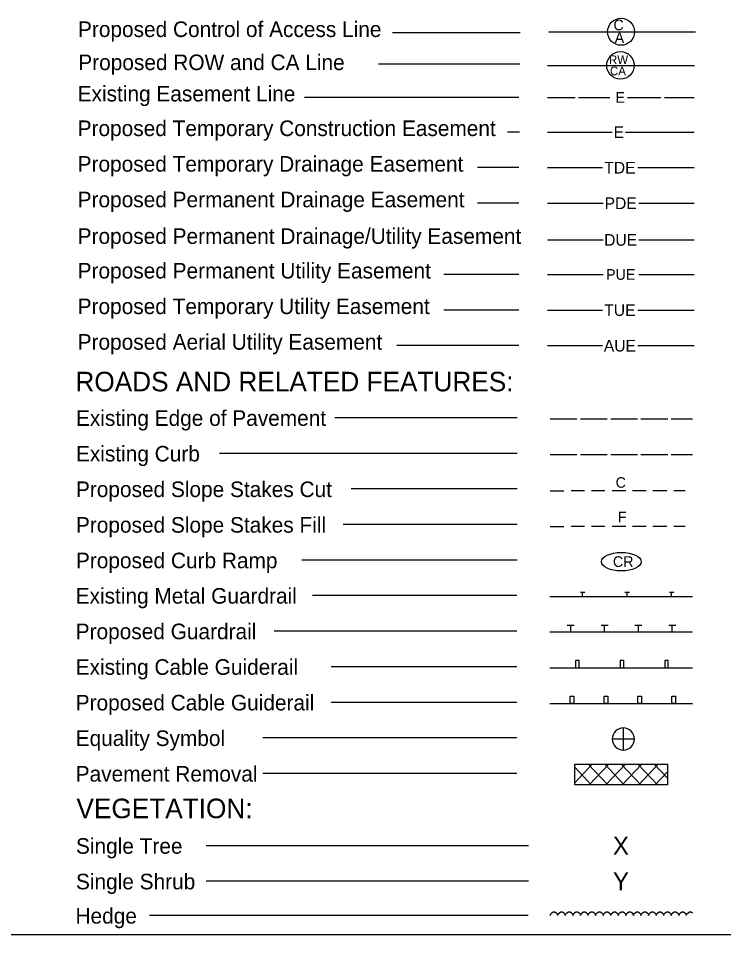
# Model space of a CAD drawing. Extents: x 2025847 to 2026166, y 840763 to 840870.
# Drawn here: x 2025880.57 to 2025913.87, y 840762.86 to 840806.14 of the extents above; entities that cross this region are included whole.
import ezdxf

# ---------------------------------------------------------------- set-up
doc = ezdxf.new("R2010")
doc.units = 0
for name, color, linetype in [('P_RDY_Easement_Permanent_Drainage_Utility', 7, 'Continuous'), ('P_RDY_WCC_CELL', 7, 'Continuous'), ('Sheet_Plan_CELL', 7, 'Continuous'), ('Sheet_Symbology_CELL', 7, 'Continuous')]:
    doc.layers.add(name, color=color, linetype=linetype)

msp = doc.modelspace()

# ---------------------------------------------------------------- linework, layer by layer
at = {"layer": 'P_RDY_Easement_Permanent_Drainage_Utility'}
for p, q in [((2025905.546, 840795.677), (2025908.178, 840795.677)), ((2025909.86, 840795.677), (2025912.483, 840795.677))]:
    msp.add_line(p, q, dxfattribs=at)
at = {"layer": 'P_RDY_WCC_CELL'}
msp.add_ellipse((2025909.036, 840780.474), major_axis=(0.943, 0), ratio=0.462467, dxfattribs=at)
at = {"layer": 'Sheet_Plan_CELL'}
msp.add_line((2025847.266, 840762.856), (2025982.68, 840762.856), dxfattribs=at)
at = {"layer": 'Sheet_Symbology_CELL'}
for p, q in [((2025904.26, 840805.465), (2025898.236, 840805.465)), ((2025905.608, 840805.497), (2025912.545, 840805.497)), ((2025904.252, 840803.972), (2025897.579, 840803.972)), ((2025905.547, 840803.907), (2025912.484, 840803.907)), ((2025904.199, 840802.406), (2025894.085, 840802.406)), ((2025905.546, 840802.406), (2025906.851, 840802.406)), ((2025907.019, 840802.406), (2025908.49, 840802.406)), ((2025909.331, 840802.406), (2025910.907, 840802.406)), ((2025911.076, 840802.406), (2025912.483, 840802.406)), ((2025904.231, 840800.771), (2025903.67, 840800.771)), ((2025905.546, 840800.771), (2025905.766, 840800.771)), ((2025905.766, 840800.771), (2025908.604, 840800.771)), ((2025909.234, 840800.771), (2025912.072, 840800.771)), ((2025912.072, 840800.771), (2025912.483, 840800.771)), ((2025904.199, 840799.089), (2025902.252, 840799.089)), ((2025905.546, 840799.089), (2025905.828, 840799.089)), ((2025905.828, 840799.089), (2025908.14, 840799.089)), ((2025909.822, 840799.089), (2025912.134, 840799.089)), ((2025912.134, 840799.089), (2025912.483, 840799.089)), ((2025904.199, 840797.408), (2025902.252, 840797.408)), ((2025905.546, 840797.408), (2025905.866, 840797.408)), ((2025905.866, 840797.408), (2025908.178, 840797.408)), ((2025909.86, 840797.408), (2025912.172, 840797.408)), ((2025912.172, 840797.408), (2025912.483, 840797.408)), ((2025904.199, 840794.044), (2025900.656, 840794.044)), ((2025905.546, 840794.044), (2025905.869, 840794.044)), ((2025905.869, 840794.044), (2025908.181, 840794.044)), ((2025909.863, 840794.044), (2025912.175, 840794.044)), ((2025912.175, 840794.044), (2025912.483, 840794.044)), ((2025904.199, 840792.362), (2025900.656, 840792.362)), ((2025905.546, 840792.362), (2025905.828, 840792.362)), ((2025905.828, 840792.362), (2025908.14, 840792.362)), ((2025909.822, 840792.362), (2025912.134, 840792.362)), ((2025912.134, 840792.362), (2025912.483, 840792.362)), ((2025904.199, 840790.681), (2025898.443, 840790.681)), ((2025905.546, 840790.681), (2025905.828, 840790.681)), ((2025905.828, 840790.681), (2025908.14, 840790.681)), ((2025909.822, 840790.681), (2025912.134, 840790.681)), ((2025912.134, 840790.681), (2025912.483, 840790.681)), ((2025904.118, 840787.273), (2025895.512, 840787.273)), ((2025905.676, 840787.225), (2025906.937, 840787.225)), ((2025907.105, 840787.225), (2025908.366, 840787.225)), ((2025908.534, 840787.225), (2025909.796, 840787.225)), ((2025909.964, 840787.225), (2025911.225, 840787.225)), ((2025911.393, 840787.225), (2025912.402, 840787.225)), ((2025904.118, 840785.592), (2025890.064, 840785.592)), ((2025905.676, 840785.543), (2025906.937, 840785.543)), ((2025907.105, 840785.543), (2025908.366, 840785.543)), ((2025908.534, 840785.543), (2025909.796, 840785.543)), ((2025909.964, 840785.543), (2025911.225, 840785.543)), ((2025911.393, 840785.543), (2025912.402, 840785.543)), ((2025904.118, 840783.91), (2025896.283, 840783.91)), ((2025905.676, 840783.822), (2025906.315, 840783.822)), ((2025907.298, 840783.822), (2025906.664, 840783.822)), ((2025908.265, 840783.822), (2025907.626, 840783.822)), ((2025909.253, 840783.822), (2025908.597, 840783.822)), ((2025910.216, 840783.822), (2025909.564, 840783.822)), ((2025911.187, 840783.822), (2025910.527, 840783.822)), ((2025912.053, 840783.822), (2025911.515, 840783.822)), ((2025904.118, 840782.229), (2025895.9, 840782.229)), ((2025905.676, 840782.14), (2025906.315, 840782.14)), ((2025907.298, 840782.14), (2025906.664, 840782.14)), ((2025908.265, 840782.14), (2025907.626, 840782.14)), ((2025909.253, 840782.14), (2025908.597, 840782.14)), ((2025910.216, 840782.14), (2025909.564, 840782.14)), ((2025911.187, 840782.14), (2025910.527, 840782.14)), ((2025912.053, 840782.14), (2025911.515, 840782.14)), ((2025904.118, 840780.547), (2025893.95, 840780.547)), ((2025904.105, 840778.876), (2025894.449, 840778.876)), ((2025905.663, 840778.827), (2025912.389, 840778.827)), ((2025907.103, 840779.037), (2025907.314, 840779.037)), ((2025907.209, 840778.827), (2025907.209, 840779.037)), ((2025909.205, 840779.037), (2025909.416, 840779.037)), ((2025909.31, 840778.827), (2025909.31, 840779.037)), ((2025911.307, 840779.037), (2025911.518, 840779.037)), ((2025911.412, 840778.827), (2025911.412, 840779.037)), ((2025904.105, 840777.194), (2025892.65, 840777.194)), ((2025912.389, 840777.146), (2025905.663, 840777.146)), ((2025906.48, 840777.478), (2025906.817, 840777.478)), ((2025906.648, 840777.146), (2025906.648, 840777.478)), ((2025908.078, 840777.478), (2025908.414, 840777.478)), ((2025908.246, 840777.146), (2025908.246, 840777.478)), ((2025909.675, 840777.478), (2025910.011, 840777.478)), ((2025909.843, 840777.146), (2025909.843, 840777.478)), ((2025911.273, 840777.478), (2025911.609, 840777.478)), ((2025911.441, 840777.146), (2025911.441, 840777.478)), ((2025904.105, 840775.512), (2025895.335, 840775.512)), ((2025905.663, 840775.464), (2025912.389, 840775.464)), ((2025904.105, 840773.831), (2025895.335, 840773.831)), ((2025905.663, 840773.783), (2025912.389, 840773.783)), ((2025909.129, 840772.625), (2025909.129, 840772.1)), ((2025904.105, 840772.149), (2025892.113, 840772.149)), ((2025908.603, 840772.1), (2025909.129, 840772.1)), ((2025909.129, 840772.1), (2025909.129, 840771.574)), ((2025909.129, 840772.1), (2025909.654, 840772.1)), ((2025906.835, 840770.912), (2025911.216, 840770.912)), ((2025906.835, 840769.929), (2025906.835, 840770.912)), ((2025906.835, 840770.862), (2025906.882, 840770.912)), ((2025906.835, 840770.025), (2025907.664, 840770.912)), ((2025907.613, 840769.929), (2025906.835, 840770.761)), ((2025908.395, 840769.929), (2025907.47, 840770.912)), ((2025907.521, 840769.929), (2025908.446, 840770.912)), ((2025909.173, 840769.929), (2025908.252, 840770.912)), ((2025908.298, 840769.929), (2025909.227, 840770.912)), ((2025909.955, 840769.929), (2025909.03, 840770.912)), ((2025909.08, 840769.929), (2025910.005, 840770.912)), ((2025910.737, 840769.929), (2025909.808, 840770.912)), ((2025909.862, 840769.929), (2025910.783, 840770.912)), ((2025911.216, 840770.244), (2025910.59, 840770.912)), ((2025911.216, 840770.912), (2025911.216, 840769.929)), ((2025904.105, 840770.468), (2025892.113, 840770.468)), ((2025910.64, 840769.929), (2025911.216, 840770.542)), ((2025911.216, 840769.929), (2025906.835, 840769.929)), ((2025904.658, 840767.059), (2025889.429, 840767.059)), ((2025904.658, 840765.377), (2025889.429, 840765.377)), ((2025904.635, 840763.758), (2025886.753, 840763.758)), ((2025905.677, 840763.758), (2025905.702, 840763.838)), ((2025905.702, 840763.838), (2025905.753, 840763.893)), ((2025905.753, 840763.893), (2025905.82, 840763.931)), ((2025905.82, 840763.931), (2025905.9, 840763.931)), ((2025905.9, 840763.931), (2025905.967, 840763.888)), ((2025905.967, 840763.888), (2025906.014, 840763.834)), ((2025906.014, 840763.834), (2025906.03, 840763.762)), ((2025906.035, 840763.758), (2025906.06, 840763.838)), ((2025906.06, 840763.838), (2025906.11, 840763.893)), ((2025906.11, 840763.893), (2025906.178, 840763.931)), ((2025906.178, 840763.931), (2025906.257, 840763.931)), ((2025906.257, 840763.931), (2025906.325, 840763.888)), ((2025906.325, 840763.888), (2025906.371, 840763.834)), ((2025906.371, 840763.834), (2025906.388, 840763.762)), ((2025906.392, 840763.758), (2025906.417, 840763.838)), ((2025906.417, 840763.838), (2025906.468, 840763.893)), ((2025906.468, 840763.893), (2025906.535, 840763.931)), ((2025906.535, 840763.931), (2025906.615, 840763.931)), ((2025906.615, 840763.931), (2025906.682, 840763.888)), ((2025906.682, 840763.888), (2025906.728, 840763.834)), ((2025906.728, 840763.834), (2025906.745, 840763.762)), ((2025906.749, 840763.758), (2025906.774, 840763.838)), ((2025906.774, 840763.838), (2025906.825, 840763.893)), ((2025906.825, 840763.893), (2025906.892, 840763.931)), ((2025906.892, 840763.931), (2025906.972, 840763.931)), ((2025906.972, 840763.931), (2025907.039, 840763.888)), ((2025907.039, 840763.888), (2025907.086, 840763.834)), ((2025907.086, 840763.834), (2025907.102, 840763.762)), ((2025907.107, 840763.758), (2025907.132, 840763.838)), ((2025907.132, 840763.838), (2025907.182, 840763.893)), ((2025907.182, 840763.893), (2025907.25, 840763.931)), ((2025907.25, 840763.931), (2025907.329, 840763.931)), ((2025907.329, 840763.931), (2025907.397, 840763.888)), ((2025907.397, 840763.888), (2025907.443, 840763.834)), ((2025907.443, 840763.834), (2025907.46, 840763.762)), ((2025907.464, 840763.758), (2025907.489, 840763.838)), ((2025907.489, 840763.838), (2025907.54, 840763.893)), ((2025907.54, 840763.893), (2025907.607, 840763.931)), ((2025907.607, 840763.931), (2025907.687, 840763.931)), ((2025907.687, 840763.931), (2025907.754, 840763.888)), ((2025907.754, 840763.888), (2025907.8, 840763.834)), ((2025907.8, 840763.834), (2025907.817, 840763.762)), ((2025907.821, 840763.758), (2025907.846, 840763.838)), ((2025907.846, 840763.838), (2025907.897, 840763.893)), ((2025907.897, 840763.893), (2025907.964, 840763.931)), ((2025907.964, 840763.931), (2025908.044, 840763.931)), ((2025908.044, 840763.931), (2025908.111, 840763.888)), ((2025908.111, 840763.888), (2025908.158, 840763.834)), ((2025908.158, 840763.834), (2025908.174, 840763.762)), ((2025908.179, 840763.758), (2025908.204, 840763.838)), ((2025908.204, 840763.838), (2025908.254, 840763.893)), ((2025908.254, 840763.893), (2025908.322, 840763.931)), ((2025908.322, 840763.931), (2025908.401, 840763.931)), ((2025908.401, 840763.931), (2025908.469, 840763.888)), ((2025908.469, 840763.888), (2025908.515, 840763.834)), ((2025908.515, 840763.834), (2025908.532, 840763.762)), ((2025908.536, 840763.758), (2025908.561, 840763.838)), ((2025908.561, 840763.838), (2025908.612, 840763.893)), ((2025908.612, 840763.893), (2025908.679, 840763.931)), ((2025908.679, 840763.931), (2025908.759, 840763.931)), ((2025908.759, 840763.931), (2025908.826, 840763.888)), ((2025908.826, 840763.888), (2025908.872, 840763.834)), ((2025908.872, 840763.834), (2025908.889, 840763.762)), ((2025908.893, 840763.758), (2025908.918, 840763.838)), ((2025908.918, 840763.838), (2025908.969, 840763.893)), ((2025908.969, 840763.893), (2025909.036, 840763.931)), ((2025909.036, 840763.931), (2025909.116, 840763.931)), ((2025909.116, 840763.931), (2025909.183, 840763.888)), ((2025909.183, 840763.888), (2025909.23, 840763.834)), ((2025909.23, 840763.834), (2025909.246, 840763.762)), ((2025909.251, 840763.758), (2025909.276, 840763.838)), ((2025909.276, 840763.838), (2025909.326, 840763.893)), ((2025909.326, 840763.893), (2025909.394, 840763.931)), ((2025909.394, 840763.931), (2025909.473, 840763.931)), ((2025909.473, 840763.931), (2025909.541, 840763.888)), ((2025909.541, 840763.888), (2025909.587, 840763.834)), ((2025909.587, 840763.834), (2025909.604, 840763.762)), ((2025909.608, 840763.758), (2025909.633, 840763.838)), ((2025909.633, 840763.838), (2025909.684, 840763.893)), ((2025909.684, 840763.893), (2025909.751, 840763.931)), ((2025909.751, 840763.931), (2025909.831, 840763.931)), ((2025909.831, 840763.931), (2025909.898, 840763.888)), ((2025909.898, 840763.888), (2025909.944, 840763.834)), ((2025909.944, 840763.834), (2025909.961, 840763.762)), ((2025909.965, 840763.758), (2025909.99, 840763.838)), ((2025909.99, 840763.838), (2025910.041, 840763.893)), ((2025910.041, 840763.893), (2025910.108, 840763.931)), ((2025910.108, 840763.931), (2025910.188, 840763.931)), ((2025910.188, 840763.931), (2025910.255, 840763.888)), ((2025910.255, 840763.888), (2025910.302, 840763.834)), ((2025910.302, 840763.834), (2025910.318, 840763.762)), ((2025910.323, 840763.758), (2025910.348, 840763.838)), ((2025910.348, 840763.838), (2025910.398, 840763.893)), ((2025910.398, 840763.893), (2025910.466, 840763.931)), ((2025910.466, 840763.931), (2025910.545, 840763.931)), ((2025910.545, 840763.931), (2025910.613, 840763.888)), ((2025910.613, 840763.888), (2025910.659, 840763.834)), ((2025910.659, 840763.834), (2025910.676, 840763.762)), ((2025910.68, 840763.758), (2025910.705, 840763.838)), ((2025910.705, 840763.838), (2025910.756, 840763.893)), ((2025910.756, 840763.893), (2025910.823, 840763.931)), ((2025910.823, 840763.931), (2025910.903, 840763.931)), ((2025910.903, 840763.931), (2025910.97, 840763.888)), ((2025910.97, 840763.888), (2025911.016, 840763.834)), ((2025911.016, 840763.834), (2025911.033, 840763.762)), ((2025911.037, 840763.758), (2025911.062, 840763.838)), ((2025911.062, 840763.838), (2025911.113, 840763.893)), ((2025911.113, 840763.893), (2025911.18, 840763.931)), ((2025911.18, 840763.931), (2025911.26, 840763.931)), ((2025911.26, 840763.931), (2025911.327, 840763.888)), ((2025911.327, 840763.888), (2025911.374, 840763.834)), ((2025911.374, 840763.834), (2025911.39, 840763.762)), ((2025911.395, 840763.758), (2025911.42, 840763.838)), ((2025911.42, 840763.838), (2025911.47, 840763.893)), ((2025911.47, 840763.893), (2025911.537, 840763.931)), ((2025911.537, 840763.931), (2025911.617, 840763.931)), ((2025911.617, 840763.931), (2025911.685, 840763.888)), ((2025911.685, 840763.888), (2025911.731, 840763.834)), ((2025911.731, 840763.834), (2025911.748, 840763.762)), ((2025911.752, 840763.758), (2025911.777, 840763.838)), ((2025911.777, 840763.838), (2025911.828, 840763.893)), ((2025911.828, 840763.893), (2025911.895, 840763.931)), ((2025911.895, 840763.931), (2025911.975, 840763.931)), ((2025911.975, 840763.931), (2025912.042, 840763.888)), ((2025912.042, 840763.888), (2025912.088, 840763.834)), ((2025912.088, 840763.834), (2025912.105, 840763.762)), ((2025912.109, 840763.758), (2025912.134, 840763.838)), ((2025912.134, 840763.838), (2025912.185, 840763.893)), ((2025912.185, 840763.893), (2025912.252, 840763.931)), ((2025912.252, 840763.931), (2025912.332, 840763.931)), ((2025912.332, 840763.931), (2025912.399, 840763.888)), ((2025912.399, 840763.888), (2025912.404, 840763.884))]:
    msp.add_line(p, q, dxfattribs=at)
for points in [[(2025906.88, 840775.464), (2025907.048, 840775.464), (2025907.048, 840775.8), (2025906.88, 840775.8)], [(2025908.982, 840775.464), (2025909.15, 840775.464), (2025909.15, 840775.8), (2025908.982, 840775.8)], [(2025911.083, 840775.464), (2025911.252, 840775.464), (2025911.252, 840775.8), (2025911.083, 840775.8)], [(2025906.626, 840774.119), (2025906.794, 840774.119), (2025906.794, 840773.783), (2025906.626, 840773.783)], [(2025908.224, 840774.119), (2025908.392, 840774.119), (2025908.392, 840773.783), (2025908.224, 840773.783)], [(2025909.821, 840774.119), (2025909.989, 840774.119), (2025909.989, 840773.783), (2025909.821, 840773.783)], [(2025911.419, 840774.119), (2025911.587, 840774.119), (2025911.587, 840773.783), (2025911.419, 840773.783)]]:
    msp.add_lwpolyline(points, close=True, dxfattribs=at)
for centre, radius in [((2025909.026, 840805.506), 0.637), ((2025908.994, 840803.92), 0.649)]:
    msp.add_circle(centre, radius, dxfattribs=at)
for start, end in [(89.9944, 179.9989), (359.9944, 89.9989), (179.9944, 269.9989), (269.9944, 359.9989)]:
    msp.add_arc((2025909.129, 840772.1), 0.525, start, end, dxfattribs=at)

# ---------------------------------------------------------------- texts
at = {"layer": 'P_RDY_Easement_Permanent_Drainage_Utility'}
msp.add_text('DUE', height=0.5507, dxfattribs=at).set_placement((2025908.228, 840795.4))
at = {"layer": 'P_RDY_WCC_CELL'}
msp.add_text('CR', height=0.5045, dxfattribs=at).set_placement((2025908.64, 840780.226))
at = {"layer": 'Sheet_Symbology_CELL'}
for s, height, p in [('C', 0.499, (2025908.665, 840805.581)), ('Proposed Control of Access Line', 0.73569, (2025883.384, 840805.26)), ('A', 0.499, (2025908.725, 840804.981)), ('Proposed ROW and CA Line', 0.73569, (2025883.399, 840803.696)), ('RW', 0.4068, (2025908.451, 840803.984)), ('CA', 0.4068, (2025908.498, 840803.455)), ('Existing Easement Line', 0.73569, (2025883.368, 840802.216)), ('E', 0.504, (2025908.759, 840802.154)), ('Proposed Temporary Construction Easement', 0.73569, (2025883.368, 840800.581)), ('E', 0.551, (2025908.676, 840800.493)), ('Proposed Temporary Drainage Easement', 0.73569, (2025883.368, 840798.899)), ('TDE', 0.5507, (2025908.233, 840798.812)), ('Proposed Permanent Drainage Easement', 0.73569, (2025883.368, 840797.217)), ('PDE', 0.5507, (2025908.25, 840797.13)), ('Proposed Permanent Drainage/Utility Easement', 0.73569, (2025883.368, 840795.487)), ('Proposed Permanent Utility Easement', 0.73569, (2025883.368, 840793.854)), ('PUE', 0.5045, (2025908.316, 840793.792)), ('Proposed Temporary Utility Easement', 0.73569, (2025883.368, 840792.172)), ('TUE', 0.5507, (2025908.233, 840792.085)), ('Proposed Aerial Utility Easement', 0.73569, (2025883.368, 840790.49)), ('AUE', 0.5507, (2025908.212, 840790.403)), ('ROADS AND RELATED FEATURES:', 0.92486, (2025883.262, 840788.521)), ('Existing Edge of Pavement', 0.73569, (2025883.287, 840786.891)), ('Existing Curb', 0.73569, (2025883.287, 840785.209)), ('C', 0.498, (2025908.77, 840783.968)), ('Proposed Slope Stakes Cut', 0.73569, (2025883.287, 840783.528)), ('F', 0.498, (2025908.871, 840782.339)), ('Proposed Slope Stakes Fill', 0.73569, (2025883.287, 840781.846)), ('Proposed Curb Ramp', 0.73569, (2025883.287, 840780.165)), ('Existing Metal Guardrail', 0.73569, (2025883.274, 840778.493)), ('Proposed Guardrail', 0.73569, (2025883.275, 840776.813)), ('Existing Cable Guiderail', 0.73569, (2025883.275, 840775.131)), ('Proposed Cable Guiderail', 0.73569, (2025883.275, 840773.449)), ('Equality Symbol', 0.73569, (2025883.275, 840771.768)), ('Pavement Removal', 0.73569, (2025883.275, 840770.086)), ('VEGETATION:', 0.92486, (2025883.311, 840768.358)), ('Single Tree', 0.73569, (2025883.288, 840766.678)), ('X', 0.841, (2025908.643, 840766.639)), ('Single Shrub', 0.73569, (2025883.288, 840764.997)), ('Y', 0.841, (2025908.643, 840764.957)), ('Hedge', 0.7357, (2025883.266, 840763.378))]:
    msp.add_text(s, height=height, dxfattribs=at).set_placement(p)

doc.saveas('drawing.dxf')
